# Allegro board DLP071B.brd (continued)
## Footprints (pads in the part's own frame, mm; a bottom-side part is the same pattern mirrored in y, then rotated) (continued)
CAP-FK-V-CASEE_PAN
  rect 1.422x4.166 smd: 1(0,-2.857) 2(0,2.857)
CAP_0402
  rect 0.508x0.508 smd: 1(-0.521,0) 2(0.521,0)
CAP_0603
  rect 1.067x1.016 smd: 1(-0.864,0) 2(0.864,0)
CAP_0805
  rect 1.27x1.524 smd: 1(-0.965,0) 2(0.965,0)
CAP_1206
  rect 1.575x1.626 smd: 1(-1.714,0) 2(1.714,0)
CAP_1210
  rect 1.575x2.591 smd: 1(-1.397,0) 2(1.397,0)
CN3_53398_MOLEX
  rect 2.108x2.997 smd: (-3.8,-1.85) (3.8,-1.85)
  rect 0.61x1.6 smd: 1(-1.25,1.063) 2(0,1.063) 3(1.25,1.063)
CN120_QTH_SAMTEC
  round 0.762 hole 1.016 unplated: (-19.24,2.03) (19.24,2.03)
  rect 0.305x1.448 smd: 1(-17.25,3.08) 2(-17.25,-3.09) 3(-16.75,3.08) 4(-16.75,-3.09) 5(-16.25,3.08) 6(-16.25,-3.09) 7(-15.75,3.08) 8(-15.75,-3.09) 9(-15.25,3.08) 10(-15.25,-3.09) 11(-14.75,3.08) 12(-14.75,-3.09) 13(-14.25,3.08) 14(-14.25,-3.09) 15(-13.75,3.08) 16(-13.75,-3.09) 17(-13.25,3.08) 18(-13.25,-3.09) 19(-12.75,3.08) 20(-12.75,-3.09) 21(-12.25,3.08) 22(-12.25,-3.09) 23(-11.75,3.08) 24(-11.75,-3.09) 25(-11.25,3.08) 26(-11.25,-3.09) 27(-10.75,3.08) 28(-10.75,-3.09) 29(-10.25,3.08) 30(-10.25,-3.09) 31(-9.75,3.08) 32(-9.75,-3.09) 33(-9.25,3.08) 34(-9.25,-3.09) 35(-8.75,3.08) 36(-8.75,-3.09) 37(-8.25,3.08) 38(-8.25,-3.09) 39(-7.75,3.08) 40(-7.75,-3.09) 41(-7.25,3.08) 42(-7.25,-3.09) 43(-6.75,3.08) 44(-6.75,-3.09) 45(-6.25,3.08) 46(-6.25,-3.09) 47(-5.75,3.08) 48(-5.75,-3.09) 49(-5.25,3.08) 50(-5.25,-3.09) 51(-4.75,3.08) 52(-4.75,-3.09) 53(-4.25,3.08) 54(-4.25,-3.09) 55(-3.75,3.08) 56(-3.75,-3.09) 57(-3.25,3.08) 58(-3.25,-3.09) 59(-2.75,3.08) 60(-2.75,-3.09) 61(2.75,3.08) 62(2.75,-3.09) 63(3.25,3.08) 64(3.25,-3.09) 65(3.75,3.08) 66(3.75,-3.09) 67(4.25,3.08) 68(4.25,-3.09) 69(4.75,3.08) 70(4.75,-3.09) 71(5.25,3.08) 72(5.25,-3.09) 73(5.75,3.08) 74(5.75,-3.09) 75(6.25,3.08) 76(6.25,-3.09) 77(6.75,3.08) 78(6.75,-3.09) 79(7.25,3.08) 80(7.25,-3.09) 81(7.75,3.08) 82(7.75,-3.09) 83(8.25,3.08) 84(8.25,-3.09) 85(8.75,3.08) 86(8.75,-3.09) 87(9.25,3.08) 88(9.25,-3.09) 89(9.75,3.08) 90(9.75,-3.09) 91(10.25,3.08) 92(10.25,-3.09) 93(10.75,3.08) 94(10.75,-3.09) 95(11.25,3.08) 96(11.25,-3.09) 97(11.75,3.08) 98(11.75,-3.09) 99(12.25,3.08) 100(12.25,-3.09) 101(12.75,3.08) 102(12.75,-3.09) 103(13.25,3.08) 104(13.25,-3.09) 105(13.75,3.08) 106(13.75,-3.09) 107(14.25,3.08) 108(14.25,-3.09) 109(14.75,3.08) 110(14.75,-3.09) 111(15.25,3.08) 112(15.25,-3.09) 113(15.75,3.08) 114(15.75,-3.09) 115(16.25,3.08) 116(16.25,-3.09) 117(16.75,3.08) 118(16.75,-3.09) 119(17.25,3.08) 120(17.25,-3.09)
  rect 2.54x0.635 smd: G1(-18.445,0) G4(-1.555,0) G5(1.555,0) G8(18.445,0)
  rect 4.699x0.635 smd: G2(-13.175,0) G3(-6.825,0) G6(6.825,0) G7(13.175,0)
CONN4-52808_MOLEX
  rect 0.61x1.448 smd: 1(-1.501,-1.778) 3(0.5,-1.778)
  rect 0.61x1.651 smd: 2(-0.5,1.778) 4(1.501,1.778)
CONN4-53398-A_MOLEX
  rect 2.108x2.997 smd: (-4.425,-2.913) (4.425,-2.913)
  rect 0.61x1.6 smd: 1(-1.875,0) 2(-0.625,0) 3(0.625,0) 4(1.875,0)
CONN4-67068-1000-A_MOLEX
  round 3.175 hole 2.286: (-5.99,10.28) (6.05,10.28)
  round 1.422 hole 0.914: 1(1.28,14.99) 2(-1.22,14.99) 3(-1.22,12.99) 4(1.28,12.99)
CONN5-53398-0590-A_MOLEX
  rect 2.108x2.997 smd: (-5.05,-1.85) (5.05,-1.85)
  rect 0.61x1.6 smd: 1(-2.5,1.063) 2(-1.25,1.063) 3(0,1.063) 4(1.25,1.063) 5(2.5,1.063)
CONN6-53398-0690-A_MOLEX
  rect 2.108x2.997 smd: (-5.675,-1.85) (5.675,-1.85)
  rect 0.61x1.6 smd: 1(-3.125,1.063) 2(-1.875,1.063) 3(-0.625,1.063) 4(0.625,1.063) 5(1.875,1.063) 6(3.125,1.063)
CONN8-43045-0813_MOLEX
  round 1.524 hole 1.016: (-11.989,3.937) (2.997,3.937) 1(0,0) 2(-2.997,0) 3(-5.994,0) 4(-8.992,0) 5(0,2.997) 6(-2.997,2.997) 7(-5.994,2.997) 8(-8.992,2.997)
CONN10-SQT-RA-REV_SAM
  rect 1.778x1.778 hole 1.27: 1(0,0)
  round 1.778 hole 1.27: 2(0,-1.999) 3(0,-3.998) 4(0,-5.997) 5(0,-7.996) 6(0,-9.995) 7(0,-11.994) 8(0,-13.993) 9(0,-15.992) 10(0,-17.991)
CONN10-SQT_SAM
  rect 1.778x1.778 hole 1.27: 1(0,0)
  round 1.778 hole 1.27: 2(0,-1.999) 3(0,-3.998) 4(0,-5.997) 5(0,-7.996) 6(0,-9.995) 7(0,-11.994) 8(0,-13.993) 9(0,-15.992) 10(0,-17.991)
CONN12-53398_MOLEX
  rect 2.108x2.997 smd: (-9.425,-1.85) (9.425,-1.85)
  rect 0.61x1.6 smd: 1(-6.875,1.063) 2(-5.625,1.063) 3(-4.375,1.063) 4(-3.125,1.063) 5(-1.875,1.063) 6(-0.625,1.063) 7(0.625,1.063) 8(1.875,1.063) 9(3.125,1.063) 10(4.375,1.063) 11(5.625,1.063) 12(6.875,1.063)
CONN12-FH12_HRS
  rect 1.854x2.184 smd: (-4.5,-2.895) (4.5,-2.895)
  rect 0.254x1.016 smd: 1(-2.75,0) 2(-2.25,0) 3(-1.75,0) 4(-1.25,0) 5(-0.75,0) 6(-0.25,0) 7(0.25,0) 8(0.75,0) 9(1.25,0) 10(1.75,0) 11(2.25,0) 12(2.75,0)
CONN12-SMT-TSM-112-SV_SAMTEC
  rect 3.175x1.27 smd: 1(-1.587,-13.97) 2(1.587,-11.43) 3(-1.587,-8.89) 4(1.587,-6.35) 5(-1.587,-3.81) 6(1.587,-1.27) 7(-1.587,1.27) 8(1.587,3.81) 9(-1.587,6.35) 10(1.587,8.89) 11(-1.587,11.43) 12(1.587,13.97)
CONN14-53047_MLX
  rect 1.016x1.016 hole 0.508: 1(0,0)
  round 1.016 hole 0.508: 2(-1.25,0) 3(-2.5,0) 4(-3.75,0) 5(-5,0) 6(-6.25,0) 7(-7.5,0) 8(-8.75,0) 9(-10,0) 10(-11.25,0) 11(-12.5,0) 12(-13.75,0) 13(-15,0) 14(-16.25,0)
CONN14-XF2M-A_OMRON
  rect 1.905x1.524 smd: (-5.003,-3.987) (5.003,-3.987)
  rect 0.254x1.295 smd: 1(3.25,0) 2(2.75,0) 3(2.25,0) 4(1.75,0) 5(1.25,0) 6(0.75,0) 7(0.25,0) 8(-0.25,0) 9(-0.75,0) 10(-1.25,0) 11(-1.75,0) 12(-2.25,0) 13(-2.75,0) 14(-3.25,0)
CONN20-TSM-110-0X-X-DV-A_SAMTEC
  rect 1.27x3.68 smd: 1(-11.43,-2.475) 2(-11.43,2.475) 3(-8.89,-2.475) 4(-8.89,2.475) 5(-6.35,-2.475) 6(-6.35,2.475) 7(-3.81,-2.475) 8(-3.81,2.475) 9(-1.27,-2.475) 10(-1.27,2.475) 11(1.27,-2.475) 12(1.27,2.475) 13(3.81,-2.475) 14(3.81,2.475) 15(6.35,-2.475) 16(6.35,2.475) 17(8.89,-2.475) 18(8.89,2.475) 19(11.43,-2.475) 20(11.43,2.475)
CONN22-B22B-PHD_JST
  rect 1.473x1.473 hole 0.965: 1(0,0)
  round 1.473 hole 0.965: 2(2,0) 3(0,2) 4(2,2) 5(0,4) 6(2,4) 7(0,6) 8(2,6) 9(0,8) 10(2,8) 11(0,10) 12(2,10) 13(0,12) 14(2,12) 15(0,14) 16(2,14) 17(0,16) 18(2,16) 19(0,18) 20(2,18) 21(0,20) 22(2,20)
CONN400-ASP-134486-01_SAM_MOD
  round 1.27 hole 1.27 unplated: (-27.19,0) (27.19,-3.05)
  round 0.64 smd: A01(24.765,-5.715) A02(23.495,-5.715) A03(22.225,-5.715) A04(20.955,-5.715) A05(19.685,-5.715) A06(18.415,-5.715) A07(17.145,-5.715) A08(15.875,-5.715) A09(14.605,-5.715) A10(13.335,-5.715) A11(12.065,-5.715) A12(10.795,-5.715) A13(9.525,-5.715) A14(8.255,-5.715) A15(6.985,-5.715) A16(5.715,-5.715) A17(4.445,-5.715) A18(3.175,-5.715) A19(1.905,-5.715) A20(0.635,-5.715) A21(-0.635,-5.715) A22(-1.905,-5.715) A23(-3.175,-5.715) A24(-4.445,-5.715) A25(-5.715,-5.715) A26(-6.985,-5.715) A27(-8.255,-5.715) A28(-9.525,-5.715) A29(-10.795,-5.715) A30(-12.065,-5.715) A31(-13.335,-5.715) A32(-14.605,-5.715) A33(-15.875,-5.715) A34(-17.145,-5.715) A35(-18.415,-5.715) A36(-19.685,-5.715) A37(-20.955,-5.715) A38(-22.225,-5.715) A39(-23.495,-5.715) A40(-24.765,-5.715) B01(24.765,-4.445) B02(23.495,-4.445) B03(22.225,-4.445) B04(20.955,-4.445) B05(19.685,-4.445) B06(18.415,-4.445) B07(17.145,-4.445) B08(15.875,-4.445) B09(14.605,-4.445) B10(13.335,-4.445) B11(12.065,-4.445) B12(10.795,-4.445) B13(9.525,-4.445) B14(8.255,-4.445) B15(6.985,-4.445) B16(5.715,-4.445) B17(4.445,-4.445) B18(3.175,-4.445) B19(1.905,-4.445) B20(0.635,-4.445) B21(-0.635,-4.445) B22(-1.905,-4.445) B23(-3.175,-4.445) B24(-4.445,-4.445) B25(-5.715,-4.445) B26(-6.985,-4.445) B27(-8.255,-4.445) B28(-9.525,-4.445) B29(-10.795,-4.445) B30(-12.065,-4.445) B31(-13.335,-4.445) B32(-14.605,-4.445) B33(-15.875,-4.445) B34(-17.145,-4.445) B35(-18.415,-4.445) B36(-19.685,-4.445) B37(-20.955,-4.445) B38(-22.225,-4.445) B39(-23.495,-4.445) B40(-24.765,-4.445) C01(24.765,-3.175) C02(23.495,-3.175) C03(22.225,-3.175) C04(20.955,-3.175) C05(19.685,-3.175) C06(18.415,-3.175) C07(17.145,-3.175) C08(15.875,-3.175) C09(14.605,-3.175) C10(13.335,-3.175) C11(12.065,-3.175) C12(10.795,-3.175) C13(9.525,-3.175) C14(8.255,-3.175) C15(6.985,-3.175) C16(5.715,-3.175) C17(4.445,-3.175) C18(3.175,-3.175) C19(1.905,-3.175) C20(0.635,-3.175) C21(-0.635,-3.175) C22(-1.905,-3.175) C23(-3.175,-3.175) C24(-4.445,-3.175) C25(-5.715,-3.175) C26(-6.985,-3.175) C27(-8.255,-3.175) C28(-9.525,-3.175) C29(-10.795,-3.175) C30(-12.065,-3.175) C31(-13.335,-3.175) C32(-14.605,-3.175) C33(-15.875,-3.175) C34(-17.145,-3.175) C35(-18.415,-3.175) C36(-19.685,-3.175) C37(-20.955,-3.175) C38(-22.225,-3.175) C39(-23.495,-3.175) C40(-24.765,-3.175) D01(24.765,-1.905) D02(23.495,-1.905) D03(22.225,-1.905) D04(20.955,-1.905) D05(19.685,-1.905) D06(18.415,-1.905) D07(17.145,-1.905) D08(15.875,-1.905) D09(14.605,-1.905) D10(13.335,-1.905) D11(12.065,-1.905) D12(10.795,-1.905) D13(9.525,-1.905) D14(8.255,-1.905) D15(6.985,-1.905) D16(5.715,-1.905) D17(4.445,-1.905) D18(3.175,-1.905) D19(1.905,-1.905) D20(0.635,-1.905) D21(-0.635,-1.905) D22(-1.905,-1.905) D23(-3.175,-1.905) D24(-4.445,-1.905) D25(-5.715,-1.905) D26(-6.985,-1.905) D27(-8.255,-1.905) D28(-9.525,-1.905) D29(-10.795,-1.905) D30(-12.065,-1.905) D31(-13.335,-1.905) D32(-14.605,-1.905) D33(-15.875,-1.905) D34(-17.145,-1.905) D35(-18.415,-1.905) D36(-19.685,-1.905) D37(-20.955,-1.905) D38(-22.225,-1.905) D39(-23.495,-1.905) D40(-24.765,-1.905) E01(24.765,-0.635) E02(23.495,-0.635) E03(22.225,-0.635) E04(20.955,-0.635) E05(19.685,-0.635) E06(18.415,-0.635) E07(17.145,-0.635) E08(15.875,-0.635) E09(14.605,-0.635) E10(13.335,-0.635) E11(12.065,-0.635) E12(10.795,-0.635) E13(9.525,-0.635) E14(8.255,-0.635) E15(6.985,-0.635) E16(5.715,-0.635) E17(4.445,-0.635) E18(3.175,-0.635) E19(1.905,-0.635) E20(0.635,-0.635) E21(-0.635,-0.635) E22(-1.905,-0.635) E23(-3.175,-0.635) E24(-4.445,-0.635) E25(-5.715,-0.635) E26(-6.985,-0.635) E27(-8.255,-0.635) E28(-9.525,-0.635) E29(-10.795,-0.635) E30(-12.065,-0.635) E31(-13.335,-0.635) E32(-14.605,-0.635) E33(-15.875,-0.635) E34(-17.145,-0.635) E35(-18.415,-0.635) E36(-19.685,-0.635) E37(-20.955,-0.635) E38(-22.225,-0.635) E39(-23.495,-0.635) E40(-24.765,-0.635) F01(24.765,0.635) F02(23.495,0.635) F03(22.225,0.635) F04(20.955,0.635) F05(19.685,0.635) F06(18.415,0.635) F07(17.145,0.635) F08(15.875,0.635) F09(14.605,0.635) F10(13.335,0.635) F11(12.065,0.635) F12(10.795,0.635) F13(9.525,0.635) F14(8.255,0.635) F15(6.985,0.635) F16(5.715,0.635) F17(4.445,0.635) F18(3.175,0.635) F19(1.905,0.635) F20(0.635,0.635) F21(-0.635,0.635) F22(-1.905,0.635) F23(-3.175,0.635) F24(-4.445,0.635) F25(-5.715,0.635) F26(-6.985,0.635) F27(-8.255,0.635) F28(-9.525,0.635) F29(-10.795,0.635) F30(-12.065,0.635) F31(-13.335,0.635) F32(-14.605,0.635) F33(-15.875,0.635) F34(-17.145,0.635) F35(-18.415,0.635) F36(-19.685,0.635) F37(-20.955,0.635) F38(-22.225,0.635) F39(-23.495,0.635) F40(-24.765,0.635) G01(24.765,1.905) G02(23.495,1.905) G03(22.225,1.905) G04(20.955,1.905) G05(19.685,1.905) G06(18.415,1.905) G07(17.145,1.905) G08(15.875,1.905) G09(14.605,1.905) G10(13.335,1.905) G11(12.065,1.905) G12(10.795,1.905) G13(9.525,1.905) G14(8.255,1.905) G15(6.985,1.905) G16(5.715,1.905) G17(4.445,1.905) G18(3.175,1.905) G19(1.905,1.905) G20(0.635,1.905) G21(-0.635,1.905) G22(-1.905,1.905) G23(-3.175,1.905) G24(-4.445,1.905) G25(-5.715,1.905) G26(-6.985,1.905) G27(-8.255,1.905) G28(-9.525,1.905) G29(-10.795,1.905) G30(-12.065,1.905) G31(-13.335,1.905) G32(-14.605,1.905) G33(-15.875,1.905) G34(-17.145,1.905) G35(-18.415,1.905) G36(-19.685,1.905) G37(-20.955,1.905) G38(-22.225,1.905) G39(-23.495,1.905) G40(-24.765,1.905) H01(24.765,3.175) H02(23.495,3.175) H03(22.225,3.175) H04(20.955,3.175) H05(19.685,3.175) H06(18.415,3.175) H07(17.145,3.175) H08(15.875,3.175) H09(14.605,3.175) H10(13.335,3.175) H11(12.065,3.175) H12(10.795,3.175) H13(9.525,3.175) H14(8.255,3.175) H15(6.985,3.175) H16(5.715,3.175) H17(4.445,3.175) H18(3.175,3.175) H19(1.905,3.175) H20(0.635,3.175) H21(-0.635,3.175) H22(-1.905,3.175) H23(-3.175,3.175) H24(-4.445,3.175) H25(-5.715,3.175) H26(-6.985,3.175) H27(-8.255,3.175) H28(-9.525,3.175) H29(-10.795,3.175) H30(-12.065,3.175) H31(-13.335,3.175) H32(-14.605,3.175) H33(-15.875,3.175) H34(-17.145,3.175) H35(-18.415,3.175) H36(-19.685,3.175) H37(-20.955,3.175) H38(-22.225,3.175) H39(-23.495,3.175) H40(-24.765,3.175) J01(24.765,4.445) J02(23.495,4.445) J03(22.225,4.445) J04(20.955,4.445) J05(19.685,4.445) J06(18.415,4.445) J07(17.145,4.445) J08(15.875,4.445) J09(14.605,4.445) J10(13.335,4.445) J11(12.065,4.445) J12(10.795,4.445) J13(9.525,4.445) J14(8.255,4.445) J15(6.985,4.445) J16(5.715,4.445) J17(4.445,4.445) J18(3.175,4.445) J19(1.905,4.445) J20(0.635,4.445) J21(-0.635,4.445) J22(-1.905,4.445) J23(-3.175,4.445) J24(-4.445,4.445) J25(-5.715,4.445) J26(-6.985,4.445) J27(-8.255,4.445) J28(-9.525,4.445) J29(-10.795,4.445) J30(-12.065,4.445) J31(-13.335,4.445) J32(-14.605,4.445) J33(-15.875,4.445) J34(-17.145,4.445) J35(-18.415,4.445) J36(-19.685,4.445) J37(-20.955,4.445) J38(-22.225,4.445) J39(-23.495,4.445) J40(-24.765,4.445) K01(24.765,5.715) K02(23.495,5.715) K03(22.225,5.715) K04(20.955,5.715) K05(19.685,5.715) K06(18.415,5.715) K07(17.145,5.715) K08(15.875,5.715) K09(14.605,5.715) K10(13.335,5.715) K11(12.065,5.715) K12(10.795,5.715) K13(9.525,5.715) K14(8.255,5.715) K15(6.985,5.715) K16(5.715,5.715) K17(4.445,5.715) K18(3.175,5.715) K19(1.905,5.715) K20(0.635,5.715) K21(-0.635,5.715) K22(-1.905,5.715) K23(-3.175,5.715) K24(-4.445,5.715) K25(-5.715,5.715) K26(-6.985,5.715) K27(-8.255,5.715) K28(-9.525,5.715) K29(-10.795,5.715) K30(-12.065,5.715) K31(-13.335,5.715) K32(-14.605,5.715) K33(-15.875,5.715) K34(-17.145,5.715) K35(-18.415,5.715) K36(-19.685,5.715) K37(-20.955,5.715) K38(-22.225,5.715) K39(-23.495,5.715) K40(-24.765,5.715)
DIO-SMA
  rect 2.489x1.702 smd: 1(-2.007,0) 2(2.007,0)
DIO-SMB
  rect 2.4x2.4 smd: 1(-2.2,0) 2(2.2,0)
FLTR_0603
  rect 1.067x1.016 smd: 1(-0.864,0) 2(0.864,0)
HDR1X3-TMM1030X-X-S_SAM
  rect 1.524x1.524 hole 1.016: 1(-2,0)
  round 1.524 hole 1.016: 2(0,0) 3(2,0)
HDR2_2MM
  rect 1.651x1.651 hole 1.143: 1(0,0)
  round 1.651 hole 1.143: 2(2,0)
HDR10X2-5103308_TYCO
  round 1.651 hole 1.067: 1(0,0) 2(2.54,0) 3(0,-2.54) 4(2.54,-2.54) 5(0,-5.08) 6(2.54,-5.08) 7(0,-7.62) 8(2.54,-7.62) 9(0,-10.16) 10(2.54,-10.16) 11(0,-12.7) 12(2.54,-12.7) 13(0,-15.24) 14(2.54,-15.24) 15(0,-17.78) 16(2.54,-17.78) 17(0,-20.32) 18(2.54,-20.32) 19(0,-22.86) 20(2.54,-22.86)
IND2-7447789002-7332_WURTH
  rect 1.803x2.21 smd: 1(0,-2.95) 2(0,2.95)
IND_0805
  rect 1.27x1.524 smd: 1(-0.965,0) 2(0.965,0)
IND_SERH
  rect 1.702x3.81 smd: 1(-2.85,0) 2(2.85,0)
IND_SRR1005
  rect 2.997x2.794 smd: 1(5.144,0) 2(-5.144,0)
JACK3-DCPOWER_CUI_MOD
  oval 1.5x3.5 hole 1x3: GND1(6,0)
  oval 3.5x1.5 hole 3x1: GND2(3,4.7)
  oval 1.5x4 hole 1x3.5: P12V_IN(0,0)
KYCON-CN9SMTA
  round 3.81 hole 3.048 unplated: (-12.495,0.775) (12.495,0.775)
  round 0.762 hole 1.524 unplated: (-7.95,0.775) (7.95,0.775)
  rect 0.8x3.7 smd: 1(-5.54,1.325) 2(-2.77,1.325) 3(0,1.325) 4(2.77,1.325) 5(5.54,1.325) 6(-4.155,1.325) 7(-1.385,1.325) 8(1.385,1.325) 9(4.155,1.325)
LCC8-MXD2125_MEMSIC
  round 0.5 smd: (0,0.65)
  rect 1.678x0.894 smd: 1(-1.815,1.27) 2(-1.815,0) 3(-1.815,-1.27) 5(1.815,-1.27) 6(1.815,0) 7(1.815,1.27)
  rect 0.894x1.678 smd: 4(0,-1.815) 8(0,1.815)
LED-0402-REV
  rect 0.508x0.508 smd: 1(0.521,0) 2(-0.521,0)
MH276-157GND-A
  round 7.01 hole 3.988: 1(0,0)
MICTOR_HPA
  round 1.27 hole 2.388 unplated: (11.43,0)
  rect 0.432x1.27 smd: 1(5.715,3.531) 2(5.715,-3.531) 3(5.08,3.531) 4(5.08,-3.531) 5(4.445,3.531) 6(4.445,-3.531) 7(3.81,3.531) 8(3.81,-3.531) 9(3.175,3.531) 10(3.175,-3.531) 11(2.54,3.531) 12(2.54,-3.531) 13(1.905,3.531) 14(1.905,-3.531) 15(1.27,3.531) 16(1.27,-3.531) 17(0.635,3.531) 18(0.635,-3.531) 19(0,3.531) 20(0,-3.531) 21(-0.635,3.531) 22(-0.635,-3.531) 23(-1.27,3.531) 24(-1.27,-3.531) 25(-1.905,3.531) 26(-1.905,-3.531) 27(-2.54,3.531) 28(-2.54,-3.531) 29(-3.175,3.531) 30(-3.175,-3.531) 31(-3.81,3.531) 32(-3.81,-3.531) 33(-4.445,3.531) 34(-4.445,-3.531) 35(-5.08,3.531) 36(-5.08,-3.531) 37(-5.715,3.531) 38(-5.715,-3.531)
  round 1.397 hole 0.889: G1(-5.08,0) G2(-2.54,0) G3(0,0) G4(2.54,0) G5(5.08,0)
POT-3314G
  rect 1.321x1.321 smd: 1(-1.156,2.756) 3(1.156,2.756)
  rect 1.981x1.321 smd: 2(0,-2.756)
PQFP24-QFN-25_SI
  oval 1.016x0.305 smd: 1(-2,1.25) 6(-2,-1.25) 13(2,-1.25) 18(2,1.25)
  rect 1.016x0.305 smd: 2(-2,0.75) 3(-2,0.25) 4(-2,-0.25) 5(-2,-0.75) 14(2,-0.75) 15(2,-0.25) 16(2,0.25) 17(2,0.75)
  oval 0.305x1.016 smd: 7(-1.25,-2) 12(1.25,-2) 19(1.25,2) 24(-1.25,2)
  rect 0.305x1.016 smd: 8(-0.75,-2) 9(-0.25,-2) 10(0.25,-2) 11(0.75,-2) 20(0.75,2) 21(0.25,2) 22(-0.25,2) 23(-0.75,2)
  round 0.61 hole 0.305: 25(-0.889,0.889)
QF48_PPAD
  rect 1.524x0.254 smd: 1(-4.445,2.752) 2(-4.445,2.252) 3(-4.445,1.751) 4(-4.445,1.251) 5(-4.445,0.751) 6(-4.445,0.25) 7(-4.445,-0.25) 8(-4.445,-0.751) 9(-4.445,-1.251) 10(-4.445,-1.751) 11(-4.445,-2.252) 12(-4.445,-2.752) 25(4.445,-2.752) 26(4.445,-2.252) 27(4.445,-1.751) 28(4.445,-1.251) 29(4.445,-0.751) 30(4.445,-0.25) 31(4.445,0.25) 32(4.445,0.751) 33(4.445,1.251) 34(4.445,1.751) 35(4.445,2.252) 36(4.445,2.752)
  rect 0.254x1.524 smd: 13(-2.752,-4.445) 14(-2.252,-4.445) 15(-1.751,-4.445) 16(-1.251,-4.445) 17(-0.751,-4.445) 18(-0.25,-4.445) 19(0.25,-4.445) 20(0.751,-4.445) 21(1.251,-4.445) 22(1.751,-4.445) 23(2.252,-4.445) 24(2.752,-4.445) 37(2.752,4.445) 38(2.252,4.445) 39(1.751,4.445) 40(1.251,4.445) 41(0.751,4.445) 42(0.25,4.445) 43(-0.25,4.445) 44(-0.751,4.445) 45(-1.251,4.445) 46(-1.751,4.445) 47(-2.252,4.445) 48(-2.752,4.445)
RES_0402
  rect 0.508x0.508 smd: 1(-0.521,0) 2(0.521,0)
RES_0603
  rect 1.067x1.016 smd: 1(-0.864,0) 2(0.864,0)
RES_0805
  rect 1.27x1.524 smd: 1(-0.965,0) 2(0.965,0)
RES_1206
  rect 1.575x1.626 smd: 1(-1.714,0) 2(1.714,0)
RES_1210
  rect 1.575x2.591 smd: 1(-1.397,0) 2(1.397,0)
RES_2010
  rect 1.778x2.591 smd: 1(-2.21,0) 2(2.21,0)
RNET8-EXB38V_PAN
  rect 0.94x0.787 smd: 1(-0.8,1.314) 4(-0.8,-1.314) 5(0.8,-1.314) 8(0.8,1.314)
  rect 0.94x0.559 smd: 2(-0.8,0.4) 3(-0.8,-0.4) 6(0.8,-0.4) 7(0.8,0.4)
RNET16-EXB-2HV_PAN
  rect 0.686x0.305 smd: 1(-0.851,1.75) 2(-0.851,1.25) 3(-0.851,0.75) 4(-0.851,0.25) 5(-0.851,-0.25) 6(-0.851,-0.75) 7(-0.851,-1.25) 8(-0.851,-1.75) 9(0.851,-1.75) 10(0.851,-1.25) 11(0.851,-0.75) 12(0.851,-0.25) 13(0.851,0.25) 14(0.851,0.75) 15(0.851,1.25) 16(0.851,1.75)
SM_TO_252_DPAK
  rect 1.6x2.997 smd: 1(-2.286,-4.318) 2(0,-4.318) 3(2.286,-4.318)
  rect 6.198x5.791 smd: 4(0,2.642)
SMC_ST
  rect 2.794x3.81 smd: 1(-3.569,0) 2(3.569,0)
SMD_49
  rect 5.643x2.007 smd: 1(-4.671,0) 2(4.671,0)
SOD-123
  rect 1.016x1.27 smd: 1(-1.778,0) 2(1.778,0)
SOIC5-DBV_TI
  rect 1.321x0.61 smd: 1(-1.187,0.95) 2(-1.187,0) 3(-1.187,-0.95) 4(1.187,-0.95) 5(1.187,0.95)
SOIC6-DBV_TI
  rect 1.321x0.61 smd: 1(-1.187,0.95) 2(-1.187,0) 3(-1.187,-0.95) 4(1.187,-0.95) 5(1.187,0) 6(1.187,0.95)
SOIC6-DRL_TI
  rect 0.356x1.067 smd: 1(-0.5,-0.828) 2(0,-0.828) 3(0.5,-0.828) 4(0.5,0.828) 5(0,0.828) 6(-0.5,0.828)
SOIC8-D_TI
  rect 1.55x0.6 smd: 1(-2.7,1.905) 2(-2.7,0.635) 3(-2.7,-0.635) 4(-2.7,-1.905) 5(2.7,-1.905) 6(2.7,-0.635) 7(2.7,0.635) 8(2.7,1.905)
SOIC8-DDA_TI
  rect 0.635x1.651 smd: 1(-1.905,-2.667) 2(-0.635,-2.667) 3(0.635,-2.667) 4(1.905,-2.667) 5(1.905,2.667) 6(0.635,2.667) 7(-0.635,2.667) 8(-1.905,2.667)
  round 0.61 hole 0.305: 9(-1.27,-0.635)
SOIC8-PW_TI
  rect 0.356x1.524 smd: 1(-0.975,-2.96) 2(-0.325,-2.96) 3(0.325,-2.96) 4(0.975,-2.96) 5(0.975,2.96) 6(0.325,2.96) 7(-0.325,2.96) 8(-0.975,2.96)
SOIC14-PW_TI
  rect 0.305x1.778 smd: 1(-1.951,-2.794) 2(-1.301,-2.794) 3(-0.65,-2.794) 4(0,-2.794) 5(0.65,-2.794) 6(1.301,-2.794) 7(1.951,-2.794) 8(1.951,2.794) 9(1.301,2.794) 10(0.65,2.794) 11(0,2.794) 12(-0.65,2.794) 13(-1.301,2.794) 14(-1.951,2.794)
SOIC16-PW_TI
  rect 0.356x1.524 smd: 1(-2.275,-2.96) 2(-1.625,-2.96) 3(-0.975,-2.96) 4(-0.325,-2.96) 5(0.325,-2.96) 6(0.975,-2.96) 7(1.625,-2.96) 8(2.275,-2.96) 9(2.275,2.96) 10(1.625,2.96) 11(0.975,2.96) 12(0.325,2.96) 13(-0.325,2.96) 14(-0.975,2.96) 15(-1.625,2.96) 16(-2.275,2.96)
SOIC20-DGV_TI
  rect 0.254x1.524 smd: 1(-1.8,-2.921) 2(-1.4,-2.921) 3(-1,-2.921) 4(-0.6,-2.921) 5(-0.2,-2.921) 6(0.2,-2.921) 7(0.6,-2.921) 8(1,-2.921) 9(1.4,-2.921) 10(1.8,-2.921) 11(1.8,2.921) 12(1.4,2.921) 13(1,2.921) 14(0.6,2.921) 15(0.2,2.921) 16(-0.2,2.921) 17(-0.6,2.921) 18(-1,2.921) 19(-1.4,2.921) 20(-1.8,2.921)
SOIC24-PW_TI
  rect 0.356x1.524 smd: 1(-3.575,-2.96) 2(-2.925,-2.96) 3(-2.275,-2.96) 4(-1.625,-2.96) 5(-0.975,-2.96) 6(-0.325,-2.96) 7(0.325,-2.96) 8(0.975,-2.96) 9(1.625,-2.96) 10(2.275,-2.96) 11(2.925,-2.96) 12(3.575,-2.96) 13(3.575,2.96) 14(2.925,2.96) 15(2.275,2.96) 16(1.625,2.96) 17(0.975,2.96) 18(0.325,2.96) 19(-0.325,2.96) 20(-0.975,2.96) 21(-1.625,2.96) 22(-2.275,2.96) 23(-2.925,2.96) 24(-3.575,2.96)
SOIC56-DGG_TI
  rect 0.305x1.524 smd: 1(-6.75,-3.775) 2(-6.25,-3.775) 3(-5.75,-3.775) 4(-5.25,-3.775) 5(-4.75,-3.775) 6(-4.25,-3.775) 7(-3.75,-3.775) 8(-3.25,-3.775) 9(-2.75,-3.775) 10(-2.25,-3.775) 11(-1.75,-3.775) 12(-1.25,-3.775) 13(-0.75,-3.775) 14(-0.25,-3.775) 15(0.25,-3.775) 16(0.75,-3.775) 17(1.25,-3.775) 18(1.75,-3.775) 19(2.25,-3.775) 20(2.75,-3.775) 21(3.25,-3.775) 22(3.75,-3.775) 23(4.25,-3.775) 24(4.75,-3.775) 25(5.25,-3.775) 26(5.75,-3.775) 27(6.25,-3.775) 28(6.75,-3.775) 29(6.75,3.775) 30(6.25,3.775) 31(5.75,3.775) 32(5.25,3.775) 33(4.75,3.775) 34(4.25,3.775) 35(3.75,3.775) 36(3.25,3.775) 37(2.75,3.775) 38(2.25,3.775) 39(1.75,3.775) 40(1.25,3.775) 41(0.75,3.775) 42(0.25,3.775) 43(-0.25,3.775) 44(-0.75,3.775) 45(-1.25,3.775) 46(-1.75,3.775) 47(-2.25,3.775) 48(-2.75,3.775) 49(-3.25,3.775) 50(-3.75,3.775) 51(-4.25,3.775) 52(-4.75,3.775) 53(-5.25,3.775) 54(-5.75,3.775) 55(-6.25,3.775) 56(-6.75,3.775)
SOT23-3_FC
  rect 1.016x1.372 smd: 1(0.94,1.092) 2(-0.94,1.092) 3(0,-1.092)
SOT23-DBV_TI
  rect 0.508x1.372 smd: 1(-0.94,-1.219) 2(0,-1.219) 3(0.94,-1.219) 4(0.94,1.219) 5(-0.94,1.219)
SOT23AVXC
  rect 1.016x1.372 smd: 1(0,-1.092) 2(-0.94,1.092) 3(0.94,1.092)
SOT23AVXD
  rect 1.016x1.372 smd: 1(-0.94,1.092) 2(0.94,1.092) 3(0,-1.092)
SOT223
  rect 1.499x2.007 smd: 1(-2.299,-3.15) 2(0,-3.15) 3(2.299,-3.15)
  rect 3.81x2.007 smd: 4(0,3.15)
SOT_323
  rect 0.762x1.067 smd: 1(0.66,0.94) 2(-0.66,0.94) 3(0,-0.94)
SSOP_8
  rect 0.305x1.6 smd: 1(-0.975,-2.235) 2(-0.325,-2.235) 3(0.325,-2.235) 4(0.975,-2.235) 5(0.975,2.136) 6(0.325,2.136) 7(-0.325,2.136) 8(-0.975,2.136)
SW_GT12
  rect 3.175x0.762 smd: (-2.603,2.54) (-2.603,-2.54) (2.603,0) 1(2.603,2.54) 3(2.603,-2.54)
TP
  round 1.219 hole 0.711: 1(0,0)
TSOP_56_48_DUAL_SKT
  round 1.27 hole 1.27 unplated: (-5.08,4.743) (5.08,4.743)
  rect 1.778x0.305 smd: 1(-9.69,6.75) 2(-9.69,6.25) 3(-9.69,5.75) 4(-9.69,5.25) 5(-9.69,4.75) 6(-9.69,4.25) 7(-9.69,3.75) 8(-9.69,3.25) 9(-9.69,2.75) 10(-9.69,2.25) 11(-9.69,1.75) 12(-9.69,1.25) 13(-9.69,0.75) 14(-9.69,0.25) 15(-9.69,-0.25) 16(-9.69,-0.75) 17(-9.69,-1.25) 18(-9.69,-1.75) 19(-9.69,-2.25) 20(-9.69,-2.75) 21(-9.69,-3.25) 22(-9.69,-3.75) 23(-9.69,-4.25) 24(-9.69,-4.75) 25(-9.69,-5.25) 26(-9.69,-5.75) 27(-9.69,-6.25) 28(-9.69,-6.75) 29(9.69,-6.75) 30(9.69,-6.25) 31(9.69,-5.75) 32(9.69,-5.25) 33(9.69,-4.75) 34(9.69,-4.25) 35(9.69,-3.75) 36(9.69,-3.25) 37(9.69,-2.75) 38(9.69,-2.25) 39(9.69,-1.75) 40(9.69,-1.25) 41(9.69,-0.75) 42(9.69,-0.25) 43(9.69,0.25) 44(9.69,0.75) 45(9.69,1.25) 46(9.69,1.75) 47(9.69,2.25) 48(9.69,2.75) 49(9.69,3.25) 50(9.69,3.75) 51(9.69,4.25) 52(9.69,4.75) 53(9.69,5.25) 54(9.69,5.75) 55(9.69,6.25) 56(9.69,6.75)
TSOPII_44
  rect 0.61x1.143 smd: 1(-8.4,-5.55) 2(-7.6,-5.55) 3(-6.8,-5.55) 4(-6,-5.55) 5(-5.2,-5.55) 6(-4.4,-5.55) 7(-3.6,-5.55) 8(-2.8,-5.55) 9(-2,-5.55) 10(-1.2,-5.55) 11(-0.4,-5.55) 12(0.4,-5.55) 13(1.2,-5.55) 14(2,-5.55) 15(2.8,-5.55) 16(3.6,-5.55) 17(4.4,-5.55) 18(5.2,-5.55) 19(6,-5.55) 20(6.8,-5.55) 21(7.6,-5.55) 22(8.4,-5.55) 23(8.4,5.55) 24(7.6,5.55) 25(6.8,5.55) 26(6,5.55) 27(5.2,5.55) 28(4.4,5.55) 29(3.6,5.55) 30(2.8,5.55) 31(2,5.55) 32(1.2,5.55) 33(0.4,5.55) 34(-0.4,5.55) 35(-1.2,5.55) 36(-2,5.55) 37(-2.8,5.55) 38(-3.6,5.55) 39(-4.4,5.55) 40(-5.2,5.55) 41(-6,5.55) 42(-6.8,5.55) 43(-7.6,5.55) 44(-8.4,5.55)
TSSOP_8
  rect 0.406x1.803 smd: 1(-0.975,-2.954) 2(-0.325,-2.954) 3(0.325,-2.954) 4(0.975,-2.954) 5(0.975,2.954) 6(0.325,2.954) 7(-0.325,2.954) 8(-0.975,2.954)
TSSOP_14
  rect 0.305x1.778 smd: 1(-1.951,-2.794) 2(-1.301,-2.794) 3(-0.65,-2.794) 4(0,-2.794) 5(0.65,-2.794) 6(1.301,-2.794) 7(1.951,-2.794) 8(1.951,2.794) 9(1.301,2.794) 10(0.65,2.794) 11(0,2.794) 12(-0.65,2.794) 13(-1.301,2.794) 14(-1.951,2.794)
unnamed#2
  round 2.362 hole 2.349 unplated: (-20.955,20.955) (-20.955,-20.955) (20.955,20.955) (20.955,-20.955)
  round 0.635 hole 0.66 unplated: (-18.989,-18.989) (18.989,18.989)
unnamed#3
  round 0.762 smd: (0,0)
VISHAY_IR_TSOP348
  rect 1.575x1.575 hole 1.067: 1(0,0)
  round 1.575 hole 1.067: 2(2.54,0) 3(5.08,0)

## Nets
GND: C1.1 C2.2 C3.2 C4.2 C5.2 C7.2 C8.2 C9.2 C10.2 C11.2 C12.2 C13.2 C14.2 C15.1 C16.1 C18.1 C19.2 C20.2 C22.1 C23.1 C24.2 C25.2 C26.1 C27.1 C29.1 C30.1 C31.1 C32.1 C33.1 C34.1 C35.1 C37.1 C38.1 C39.1 C40.1 C41.1 C42.1 C503.1 C504.1 C506.1 C508.1 C509.1 C511.1 C512.1 C513.2 C515.1 C516.1 C517.1 C518.1 C519.1 C520.1 C521.1 C522.1 C523.2 C524.1 C525.1 C526.2 C527.2 C528.2 C529.2 C530.2 C531.2 C532.2 C533.2 C534.2 C535.2 C536.2 C537.2 C538.2 C539.1 C540.2 C541.2 C542.2 C543.2 C544.2 C547.2 C548.1 C552.1 C553.2 C554.2 C555.2 C556.2 C557.2 C558.2 C559.2 C560.2 C561.2 C562.2 C563.2 C564.2 C565.2 C566.2 C567.2 C568.2 C569.2 C570.2 C571.2 C572.2 C573.1 C574.1 C575.2 C576.2 C577.2 C578.2 C579.2 C580.2 C581.2 C582.2 C583.2 C584.2 C585.2 C586.2 C587.2 C588.2 C589.2 C590.2 C591.2 C592.2 C593.2 C594.2 C595.2 C596.2 C597.2 C598.2 C599.2 C600.2 C601.2 C602.2 C603.1 C604.1 C605.1 C606.2 C607.1 C608.2 C611.1 C612.1 C613.2 C614.2 C615.2 C616.2 C617.2 C618.2 C619.2 C620.2 C621.2 C622.2 C623.2 C624.2 C625.2 C626.2 C627.2 C628.2 C629.1 C630.1 C631.2 C632.1 C633.1 C635.2 C636.2 C637.2 C638.2 C639.2 C640.1 C641.1 C643.1 C644.1 C645.1 C646.1 C647.1 C648.1 C649.1 C650.1 C651.1 C652.1 C653.1 C654.2 C655.1 C656.1 C657.1 C658.1 C659.1 C660.1 C661.1 C662.1 C663.1 C664.1 C665.1 C666.1 C667.1 C668.1 C669.1 C670.1 C671.1 C672.1 C673.1 C674.1 C675.1 C676.1 D1.2 D2.2 D3.2 D4.2 D6.2 D7.2 D8.2 D9.2(CATHODE) D10.2(CATHODE) D501.2 D502.2 D503.2 D504.2 D505.2 D506.2 D507.2 DN500.1 DN501.1 DN502.1 DN503.1 DN505.1 DN506.1 DN507.1 DN508.1 J1.G1 J1.G2 J1.G3 J1.G4 J1.G5 J1.G6 J1.G7 J1.G8 J2.G1 J2.G2 J2.G3 J2.G4 J2.G5 J2.G6 J2.G7 J2.G8 J4.4 J5.2 J6.2 J7.5 J8.2 J14.5 J15.5 J16.5 J17.5 J18.7 J18.10 J18.15 J18.16 J19.1 J19.16 J19.17 J19.18 J19.19 J19.20 J20.2 J22.GND1 J22.GND2(3) J23.4 J23.6 J23.8 J23.10 J23.12 J23.14 J23.16 J23.18 J23.20 J24.5 J25.3 J26.3 J27.5 J27.G1 J27.G2 J27.G3 J27.G4 J27.G5 J28.9 J28.10 J28.11 J28.12 J30.3 J32.1 J32.3 J32.5 J32.7 J33.1 J35.13 J35.14 J36.4 J37.3 J38.3 J39.3 J42.6 J43.6 J45.2 J47.9 J47.10 J47.14 J48.2 J49.4 J50.4 J51.4 J52.3 J53.3 J54.3 J54.5 J54.7 J54.9 J54.11 J55.3 J57.3 J59.3 J60.3 J61.3 J62.3 J63.A01 J63.A03 J63.A04 J63.A05 J63.A07 J63.A08 J63.A09 J63.A11 J63.A12 J63.A13 J63.A15 J63.A16 J63.A17 J63.A19 J63.A20 J63.A21 J63.A23 J63.A24 J63.A25 J63.A27 J63.A28 J63.A29 J63.A31 J63.A32 J63.A33 J63.A35 J63.A36 J63.A37 J63.A39 J63.A40 J63.B02 J63.B03 J63.B05 J63.B06 J63.B07 J63.B09 J63.B10 J63.B11 J63.B13 J63.B14 J63.B15 J63.B17 J63.B18 J63.B19 J63.B22 J63.B23 J63.B25 J63.B26 J63.B27 J63.B29 J63.B30 J63.B31 J63.B33 J63.B34 J63.B35 J63.B37 J63.B38 J63.B39 J63.C01 J63.C03 J63.C04 J63.C05 J63.C07 J63.C08 J63.C09 J63.C12 J63.C13 J63.C16 J63.C17 J63.C20 J63.C21 J63.C24 J63.C25 J63.C28 J63.C29 J63.C32 J63.C33 J63.C36 J63.C38 J63.C40 J63.D02 J63.D03 J63.D06 J63.D07 J63.D10 J63.D13 J63.D16 J63.D19 J63.D22 J63.D25 J63.D28 J63.D37 J63.D39 J63.E01 J63.E04 J63.E05 J63.E08 J63.E11 J63.E14 J63.E17 J63.E20 J63.E23 J63.E26 J63.E29 J63.E32 J63.E35 J63.E38 J63.E40 J63.F02 J63.F03 J63.F06 J63.F09 J63.F12 J63.F15 J63.F18 J63.F21 J63.F24 J63.F27 J63.F30 J63.F33 J63.F36 J63.F39 J63.G01 J63.G04 J63.G05 J63.G08 J63.G11 J63.G14 J63.G17 J63.G20 J63.G23 J63.G26 J63.G29 J63.G32 J63.G35 J63.G38 J63.G40 J63.H03 J63.H06 J63.H09 J63.H12 J63.H15 J63.H18 J63.H21 J63.H24 J63.H27 J63.H30 J63.H33 J63.H36 J63.H39 J63.J01 J63.J04 J63.J05 J63.J08 J63.J11 J63.J14 J63.J17 J63.J20 J63.J23 J63.J26 J63.J29 J63.J32 J63.J35 J63.J38 J63.J40 J63.K02 J63.K03 J63.K06 J63.K09 J63.K12 J63.K15 J63.K18 J63.K21 J63.K24 J63.K27 J63.K30 J63.K33 J63.K36 J63.K39(GND#K39) MT1.1 MT2.1 MT3.1 MT4.1 MT5.1 MT6.1 Q3.1(EMITTER) Q4.1(EMITTER) Q501.1(EMITTER) Q502.1(EMITTER) Q503.1(EMITTER) Q504.1(EMITTER) Q507.1(EMITTER) R6.2 R31.2 R44.2 R60.2 R510.1 R516.2 R521.2 R523.1 R526.1 R529.1 R534.1 R559.2 R562.1 R571.1 R572.1 R573.1 R603.1 R604.1 R605.1 R617.1 R632.1 R646.1 R651.2 R652.1 R661.1 R663.1 R665.1 R670.2 R683.2 R688.2 R690.2 R721.2 R724.1 R736.1 R744.2 R745.2 R757.1 R764.1 RN500.5 RN500.6 RN500.7 RN500.8 RN501.5 RN501.6 RN501.7 RN501.8 RN502.5 RN502.6 RN502.7 RN502.8 TP36.1 U1.2 U2.7 U2.19 U2.44 U3.3 U3.7 U4.8 U4.19 U4.38 U4.49 U5.2 U5.3 U6.15 U7.5 U7.9 U8.1 U8.12 U8.13 U9.4 U10.4 U11.A1 U11.A2 U11.A3 U11.A17 U11.A18 U11.A24 U11.A25 U11.A26 U11.AA6 U11.AA9 U11.AA12 U11.AA15 U11.AA18 U11.AA21 U11.AB5 U11.AB14 U11.AB15 U11.AB16 U11.AB17 U11.AB22 U11.AC4 U11.AC6 U11.AC17 U11.AC18 U11.AC23 U11.AD3 U11.AD17 U11.AD18 U11.AD24 U11.AE3 U11.AE17 U11.AE24 U11.AE25 U11.AF1 U11.AF2 U11.AF3 U11.AF17 U11.AF24 U11.AF25 U11.AF26 U11.B1 U11.B2 U11.B3 U11.B17 U11.B18 U11.B25 U11.C3 U11.C18 U11.C24 U11.D4 U11.D17 U11.D18 U11.D23 U11.E5 U11.E15 U11.E16(VTEST4) U11.E17 U11.E22 U11.F6 U11.F9 U11.F12 U11.F15 U11.F18 U11.F21 U11.G5 U11.J5 U11.J6 U11.J21 U11.K5 U11.K26 U11.L5 U11.L12 U11.L13 U11.L14 U11.L15 U11.L23 U11.L25 U11.M6 U11.M11 U11.M12 U11.M13 U11.M14 U11.M15 U11.M16 U11.M21 U11.M22 U11.M25 U11.N5 U11.N11 U11.N12 U11.N13 U11.N14 U11.N15 U11.N16 U11.P11 U11.P12 U11.P13 U11.P14 U11.P15 U11.P16 U11.P24 U11.R5 U11.R6 U11.R11 U11.R12 U11.R13 U11.R14 U11.R15 U11.R16 U11.R24 U11.R26 U11.T12 U11.T13 U11.T14 U11.T15 U11.U5 U11.V5 U11.V6 U11.V21 U11.W5 U11.Y5 U12.15 U13.12 U13.34 U14.1 U14.33 U14.52 U14.56 U15.7 U15.19 U15.44 U16.4 U16.7(WP) U18.3 U19.3 U20.2 U21.19 U21.25 U22.2 U500.3 U501.8 U501.10 U502.2 U503.3 U504.3 U505.14(VSS) U506.3 U507.8 U507.10 U507.11 U508.1 U508.3 U509.2 U509.8 U509.10 U510.1 U510.3 U511.1 U511.2 U512.4 U513.3 U514.2 U514.3 U515.1 U515.12 U515.13 U516.1 U516.7 U516.8 U516.9 U516.10 U516.19 U517.1 U517.9 U517.10 U517.12 U517.13 U518.3 U519.4 U520.1 U520.3 U521.1 U521.3 U522.1 U522.3 U523.3 U524.1 U524.3 VR1.1 VR2.1
P5V: C3.1 C5.1 C672.2 J1.9 J1.11 J2.9 J2.11 J14.8 J15.8 J53.1 J54.1 Q506.2(S) R27.1 R618.1 R698.2 R746.2 R766.1 R777.1 TP25.1
P5V_CONN: J32.4 R698.1
P5V_IR: C506.2 R508.1 U1.3
P5V_IR_CONN: C42.2 R74.1 U22.3
P12V: C19.1 C20.1 C505.2 C512.2 C518.2 C519.2 C606.1 C607.2 C609.2 C631.1 C632.2 C633.2 C639.1 C673.2 DN500.2 DN501.2 DN502.2 DN503.2 DN505.2 DN506.2 DN507.2 DN508.2 J18.2 J31.2 J35.1 J35.2 J52.1 J63.C35 J63.C37 Q5.2 Q5.4 R2.1 R16.2 R22.2 R550.1 R611.2 R691.1 R700.1 R701.1 R718.2 R719.2 R720.2 R747.2 R748.2 R749.2 TP43.1 U2.9 U2.22 U2.23 U2.27 U2.37 U2.42 U2.43 U7.8 U15.9 U15.22 U15.27 U15.37 U15.42
P12V_FIL: C33.2 C36.1 FB1.2 J31.1 Q5.3(S) R45.2 R47.1 R48.1 TP45.1
P12V_IN: C32.2 FB1.1 J22.P12V_IN J32.6
VDD1_INDEX_SENSE: C670.2 J57.1 R771.1
VDD2_INDEX_SENSE: C671.2 J55.1 R772.1
VDD_TILT: C508.2 R515.1 U3.8
3D_TOGGLE: U11.E26 U517.8 U520.2
A1P8V: R558.1 R594.1
A1P8V_SENSE: C27.2 C610.2 R594.2 R610.1 R616.2 TP32.1 U15.29
A_BLU_PWM: J18.5 J19.7 U8.21
A_GRN_PWM: J18.3 J19.5 U8.22
A_LED4_PWM: J18.9 J19.2 U8.20
A_LED5_PWM: J18.11 J19.4 U8.19
A_LED6_PWM: J18.13 J19.6 U8.18
A_LED7_PWM: J18.17 J19.11 U8.17
A_LED8_PWM: J18.19 J19.13 U8.16
A_RED_PWM: J18.1 J19.3 U8.23
A_SPARE_1: J18.18 J33.2 U517.23
A_SPARE_2: J18.22 U8.15(Y9)
A_SPARE_3: J18.20 U8.14
A_SSP0_CLK: R37.2 R38.2 R680.2 TP46.1 U11.AD4
A_SSP0_RXD: R625.1 R671.1 R672.1 U11.AD5
A_SSP0_TXD: R621.1 R623.1 U11.AB7
ADC_CSZ: J54.10 R597.1 TP64.1
ADC_RST/COMP_PWM: J54.2 R596.1 R694.2 TP55.1
ADC_SCLK: J54.4 R598.1 TP56.1
ADC_SDIN: J21.1 J54.6 TP57.1
ADC_SDO: J29.1 J54.8 TP58.1
AFE_CLK: R579.2 U11.AD12
AFE_RSTZ: J2.108 R9.1 U11.AC12
ALF_CLAMP: J2.116 U11.AB12
ALF_COAST: J2.118 U11.AC11
ALF_CSYNC: J2.49 TP2.1 U11.AE11
ALF_HSYNC: J2.51 TP24.1 U11.AD11
ALF_VSYNC: J2.50 TP1.1 U11.AF11
BLU_LED_EN: J40.1 RN500.3 U517.7
BLU_PWM: RN501.2 U8.4 U11.C20
BT656_A_CLK: J2.94 U4.5
BT656_A_D0: J2.105 U4.28
BT656_A_D1: J2.104 U4.26
BT656_A_D2: J2.103 U4.24
BT656_A_D3: J2.102 U4.22
BT656_A_D4: J2.101 U4.20
BT656_A_D5: J2.100 U4.16
BT656_A_D6: J2.99 U4.14
BT656_A_D7: J2.98 U4.12
BT656_A_D8: J2.97 U4.10
BT656_A_D9: J2.96 U4.7
BT656_B_CLK: J1.94 U4.4
BT656_B_D0: J1.105 U4.27
BT656_B_D1: J1.104 U4.25
BT656_B_D2: J1.70 J1.103 R503.1 U4.23
BT656_B_D3: J1.102 U4.21
BT656_B_D4: J1.101 U4.18
BT656_B_D5: J1.100 U4.15
BT656_B_D6: J1.99 R557.1 U4.13
BT656_B_D7: J1.98 U4.11
BT656_B_D8: J1.97 U4.9
BT656_B_D9: J1.96 U4.6
BT656_CLK: R537.2 U4.52
BT656_D0: R547.2 U4.30
BT656_D1: R546.2 U4.32
BT656_D2: R545.2 U4.34
BT656_D3: R544.2 U4.36
BT656_D4: R543.2 U4.39
BT656_D5: R542.2 U4.41
BT656_D6: R541.2 U4.43
BT656_D7: R540.2 U4.45
BT656_D8: R539.2 U4.47
BT656_D9: R538.2 U4.50
BUS_SELECT: J2.89 R745.1 U21.16
COMP_SENSE_INPUT: J26.2 R704.1 U512.2
COMP_SENSE_VDD: C649.2 J26.1 R703.1
COMP_SENSOR: J21.3 R705.1 R706.1 U512.1
CSZ5_DAD2: J63.B28 R65.1
CW_INDEX1: J1.82 R750.1 R751.1 TP61.1 U11.AF7 U519.1
CW_INDEX2: R568.2 R753.1 R755.1 TP60.1 U519.7(OUT)
CW_PWM1: R32.1 U11.AD8
CW_PWM2/SPD4: R517.1 U11.H26 U515.7
CWCTR1: C549.1 C550.1 C551.1 DN508.3 J58.1 U15.13
CWCTR2: C500.1 C501.1 C502.1 DN502.3 J56.1 U2.13
CWY1A: DN505.3 J58.4 R576.2 R609.2
CWY1B: DN506.3 J58.3 R25.2 R577.2
CWY1C: DN507.3 J58.2 R28.2 R563.2
CWY2A: DN500.3 J56.4 R7.2 R500.2
CWY2B: DN501.3 J56.3 R5.2 R501.2
CWY2C: DN503.3 J56.2 R4.2 R502.2
DA0: C615.1 R628.1 U11.AB8
DA1: C616.1 R629.1 U11.AF4
DA2: C618.1 R673.1 U11.AE5
DA3: C621.1 R635.1 U11.AD6
DADADD0: J63.A14 R628.2
DADADD1: J63.A18 R629.2
DADADD2: J63.A22 R673.2
DADADD3: J63.A26 R635.2
DADINTZ: J63.B08 R595.2 R713.2
DADMD0: J63.A06 R634.2
DADMD1: J63.A10 R627.2
DADOEZ: J63.B04 R633.2 R714.2
DADSEL0: J63.A30 R626.2
DADSEL1: J63.A34 R630.2
DADSTB: J63.A38 R636.2 TP47.1
DB/RED_PWM: R757.2 RN500.4 U8.2 U11.B19 U521.2
DINTZ: C578.1 R595.1 U11.AC8
DM0: C620.1 R634.1 U11.AE6
DM1: C614.1 R627.1 U11.AD7
DMD_P3P3V: C35.2 C39.2 FB2.1 FB3.1 J46.2 R66.1 R712.1 R713.1 R714.1
DMDP3P3VA: C40.2 FB3.2 J63.C39
DMDP3P3VB: C34.2 FB2.2 J63.D38
DMDSPARE0: J63.B16 R44.1
DOEZ: C619.1 R633.1 U11.AE7
DRV_RST/SSP2_CSZ_1: U11.K22 U516.6
DS0: C613.1 R626.1 U11.AC7
DS1: C617.1 R630.1 U11.AE4
DSP_P1P8V: C10.1 C13.1 J1.6 J1.8 J2.6 J2.8 J12.2
DSTB: C622.1 R636.1 U11.AF5
DYN_BLK_BUF: R756.2 U521.4
EXT_ARSTZ: J63.A02 R8.2 R10.1 R767.1 TP4.1 U11.T24
EXT_CLK: J2.52 R579.1
FAN1_LOCKD: J59.2 R71.1 U11.B24
FAN1_SW: D507.1(C) L505.2 R770.1 U15.40
FAN2_LOCKD: J60.2 R72.1 U11.D21
FAN2_SW: D506.1(C) L504.2 R769.1 U15.39
FAN3_LOCKD: J61.2 R73.1 U11.C23
FAN3_SW: D505.1(C) L503.2 R768.1 U15.38
FAN4_LOCKD: J37.2 R57.1 R581.2
FAN4_SW: D504.1(C) L502.2 R734.1 U2.40
FAN5_LOCKD: J38.2 R58.1 R567.2
FAN5_SW: D503.1(C) J3.1 L501.2 R733.1 U2.39
FAN6_LOCKD: J39.2 R59.1 R583.2
FAN6_SW: D502.1(C) J3.3 L500.2 R732.1
FAN6_SW_JUMP: J3.2 U2.38
FE_P1P2V: C9.1 C12.1 J1.2 J1.4 J2.2 J2.4 J13.2
FE_RST: J36.1 R56.2 U18.2
FIELD: J2.88 J36.3 U11.AF9
FLASH_A19_A21: R687.2 R689.2 U14.11
FLASH_A21_VPP: R685.1 R686.2 U14.15
FLASH_CSSZ: R585.2 U14.32
FLASH_CSZ: R585.1 U11.E12
FLASH_RSTZ: R552.1 R553.1 U14.14
FREQ_SENSOR: J25.2 J29.3
GPIO_12: R513.1 R514.1 U11.B22
GPIO_13: R13.1 R14.1 U11.C21
GPIO_21: RN503.3 U8.10 U11.E20
GPIO_23: RN503.4 U8.11 U11.E21
GPIO_24: J9.2 U11.B26
GPIO_26: J40.2 U11.D24
GPIO_30: R564.2 U11.D25
GPIO_32: R565.2 U11.E24
GPIO_33: R560.2 U11.D26
GPIO_40: R547.1 U11.T23
GPIO_41: R546.1 U11.R22
GPIO_42: R545.1 U11.U26
GPIO_43: R544.1 U11.U25
GPIO_44: R543.1 U11.U24
GPIO_45: R542.1 U11.U23
GPIO_46: R541.1 U11.T22
GPIO_47: R540.1 U11.V26
GPIO_48: R539.1 U11.V25
GPIO_49: R538.1 U11.V24
GPIO_50: R537.1 U11.V23
GPIO_54: RN502.4 U11.F26 U517.2
GPIO_60: R580.1 R581.1 U11.H22
GPIO_61: R566.1 R567.1 U11.H23
GPIO_62: R569.1 R570.1 U11.H24
GPIO_63: R561.1 R568.1 U11.H25
GPIO_65: R582.1 R583.1 U11.J22
GPIO_74: J21.2 U11.AE10
GPIO_75: J29.2 R599.1
GPIO_81: J24.4 U11.AB10
GPIOX_11: R67.1 U21.12
GPIOX_12: R68.1 U21.13
GPIOX_13: R69.1 U21.14
GPIOX_14: R70.1 U21.15
GPIOX_INT: R737.1 U11.E3 U21.24
GPIOX_RST: R744.1 U11.G22 U21.20
GRN_LED_EN: RN500.2 U11.C25 U517.6
GRN_PWM: RN501.1 U8.3 U11.B20
HDMI_CEC: J2.13 TP5.1 U11.G23
HDMI_HPD: J2.90 U21.10
HDMI_INT: J2.91 TP18.1 U11.AB13
HOLD_BOOTZ: J8.1 R548.2 U11.F24
I2C_BUSY: J36.2 R735.2 U11.G24
ICE_RSTZ: J23.15 J27.9 R697.1 U510.2 U511.4(\ \R\E\S\E\T)
ICTSEN: R559.1 U11.M24
INDEX1_SENSE_INPUT: J57.2 R752.1 U519.2
INDEX2_SENSE_INPUT: J55.2 R754.1 U519.6
IR0: U11.C26 U500.4
IR1: U11.E23 U518.4
KEYPD_DOWN: J47.4 R731.1 U21.2
KEYPD_LED_HOT: R725.2 U21.9
KEYPD_LED_LMP: R741.2 U21.8
KEYPD_LED_PWR: R742.2 U21.7
KEYPD_LEFT: J47.5 R729.1 U21.3
KEYPD_PWR: J47.7 R588.1 R727.1 U19.2
KEYPD_PWR_BUF: U19.4 U21.1
KEYPD_RIGHT: J47.6 R730.1 U21.4
KEYPD_SEL: J47.2 R743.1 U21.6
KEYPD_UP: J47.3 R728.1 U21.5
LAMPLITZ: J33.4 J34.1 J48.1 R774.1 R775.1
LAMPLITZ_FLTR: C675.2 R775.2 TP63.1 U522.2
LED1_GRN: D14.2(CATHODE) R68.2
LED1_RED: D15.2(CATHODE) R67.2
LED2_GRN: D12.2(CATHODE) R70.2
LED2_RED: D13.2(CATHODE) R69.2
LED4_PWM: RN501.3 U8.5 U11.A20
LED5_PWM: RN501.4 U8.6 U11.A21
LED6_PWM: RN502.1 U8.7 U11.B21
LED7_PWM: RN502.2 U8.8 U11.A22
LED8_PWM: RN502.3 U8.9 U11.A23
LED_DIN: J43.2 J44.3 R721.1 R722.2 TP50.1
LED_DIR: J43.5 R739.2 TP51.1
LED_DOUT: J43.3 R759.2 TP53.1
LED_EN: J33.3 J41.2
LED_OE: J43.4 R761.2 TP52.1
LED_SCLK: J43.1 R758.2 TP54.1
LMP_HOT: J6.1 J9.3 R528.2
LMP_TXD: J40.3 R763.1 R764.2 U524.2
LMP_TXD_BUF: J48.5 R778.1
LMPCTRL: R668.2 R670.1 TP22.1 U11.AC9 U508.2 U517.3
LMPCTRL_BUF: J48.6 R622.1
LMPCTRL_Z: J48.4 R669.1
LMPSTAT: U11.AF8 U522.4
LP_DRIVE: R574.1 R575.1 U505.5
LP_IR0: R590.1 U1.1 U500.2
LP_IR1: R593.1 U22.1 U518.2
LP_P1_0: R588.2 U505.2
LP_P1_5: R590.2 U505.7
LP_P1_6: R593.2 U505.8
LP_P2_6: R591.2 U505.13
LP_P2_7: R592.2 U505.12
LP_P3P3V: C503.2 C504.2 R504.1 R505.1 U500.5(VCC) U518.5(VCC)
LP_TA0: R589.2 U505.3
LP_TCK: J17.2 R608.1
LP_TDO_TDI: C605.2 J17.4 R606.1 U505.10
LP_TEST_VPP: J17.3 R608.2 U505.11
M_DCLKA_N: J63.K05 U11.V3
M_DCLKA_P: J63.K04 U11.V4
M_DCLKB_N: J63.J03 U11.J4
M_DCLKB_P: J63.J02 U11.J3
M_DDA00_N: J63.D21 U11.P3
M_DDA00_P: J63.D20 U11.P4
M_DDA01_N: J63.C23 U11.P1
M_DDA01_P: J63.C22 U11.P2
M_DDA02_N: J63.H23 U11.R3
M_DDA02_P: J63.H22 U11.R4
M_DDA03_N: J63.G22 U11.R1
M_DDA03_P: J63.G21 U11.R2
M_DDA04_N: J63.H26 U11.T3
M_DDA04_P: J63.H25 U11.T4
M_DDA05_N: J63.G25 U11.T1
M_DDA05_P: J63.G24 U11.T2
M_DDA06_N: J63.D24 U11.U3
M_DDA06_P: J63.D23 U11.U4
M_DDA07_N: J63.H29 U11.U1
M_DDA07_P: J63.H28 U11.U2
M_DDA08_N: J63.G28 U11.W3
M_DDA08_P: J63.G27 U11.W4
M_DDA09_N: J63.D27 U11.W1
M_DDA09_P: J63.D26 U11.W2
M_DDA10_N: J63.C27 U11.Y1
M_DDA10_P: J63.C26 U11.Y2
M_DDA11_N: J63.H32 U11.Y3
M_DDA11_P: J63.H31 U11.Y4
M_DDA12_N: J63.G31 U11.AA1
M_DDA12_P: J63.G30 U11.AA2
M_DDA13_N: J63.H35 U11.AA3
M_DDA13_P: J63.H34 U11.AA4
M_DDA14_N: J63.G34 U11.AB1
M_DDA14_P: J63.G33 U11.AB2
M_DDA15_N: J63.H38 U11.AC1
M_DDA15_P: J63.H37 U11.AC2
M_DDB00_N: J63.K26 U11.N2
M_DDB00_P: J63.K25 U11.N1
M_DDB01_N: J63.J25 U11.N4
M_DDB01_P: J63.J24 U11.N3
M_DDB02_N: J63.F23 U11.M1
M_DDB02_P: J63.F22 U11.M2
M_DDB03_N: J63.E22 U11.M4
M_DDB03_P: J63.E21 U11.M3
M_DDB04_N: J63.F26 U11.L2
M_DDB04_P: J63.F25 U11.L1
M_DDB05_N: J63.E25 U11.L4
M_DDB05_P: J63.E24 U11.L3
M_DDB06_N: J63.K29 U11.K2
M_DDB06_P: J63.K28 U11.K1
M_DDB07_N: J63.J28 U11.K4
M_DDB07_P: J63.J27 U11.K3
M_DDB08_N: J63.F29 U11.H2
M_DDB08_P: J63.F28 U11.H1
M_DDB09_N: J63.E28 U11.H4
M_DDB09_P: J63.E27 U11.H3
M_DDB10_N: J63.K32 U11.G2
M_DDB10_P: J63.K31 U11.G1
M_DDB11_N: J63.J31 U11.G4
M_DDB11_P: J63.J30 U11.G3
M_DDB12_N: J63.F32 U11.F2
M_DDB12_P: J63.F31 U11.F1
M_DDB13_N: J63.E31 U11.F4
M_DDB13_P: J63.E30 U11.F3
M_DDB14_N: J63.K35 U11.E2
M_DDB14_P: J63.K34 U11.E1
M_DDB15_N: J63.J34 U11.D2
M_DDB15_P: J63.J33 U11.D1
M_SCTRLA_N: J63.G37 U11.V1
M_SCTRLA_P: J63.G36 U11.V2
M_SCTRLB_N: J63.F35 U11.J2
M_SCTRLB_P: J63.F34 U11.J1
MAN_RSTZ: J20.1 R696.1 SW1.3 U511.3
MC_VCC: C547.1 C574.2 R587.2 R606.2 U505.1
MODEB: J45.1 J63.B12 R66.2
MTR_ARSTZ: R36.2 TP15.1 U2.48(RESETZ) U11.T25 U15.48(RESETZ)
OCLKA: R578.1 U2.6 U15.6
OCLKA_RES: R578.2 U11.AF6
OUT1A: R609.1 U15.12
OUT1A_SNUB: C549.2 R576.1
OUT1B: R25.1 U15.15
OUT1B_SNUB: C550.2 R577.1
OUT1C: R28.1 U15.16
OUT1C_SNUB: C551.2 R563.1
OUT2A: R7.1 U2.12
OUT2A_SNUB: C500.2 R500.1
OUT2B: R5.1 U2.15
OUT2B_SNUB: C501.2 R501.1
OUT2C: R4.1 U2.16
OUT2C_SNUB: C502.2 R502.1
P1_A0: J2.85 U11.AE12
P1_A1: J2.84 U11.AF12
P1_A2: J2.83 U11.AF13
P1_A3: J2.82 U11.AF14
P1_A4: J2.81 U11.AC13
P1_A5: J2.80 U11.AD13
P1_A6: J2.79 U11.AE13
P1_A7: J2.78 U11.AE14
P1_A8: J2.77 U11.AE15
P1_A9: J2.76 U11.AD15
P1_B0: J2.75 U11.AD14
P1_B1: J2.74 U11.AC14
P1_B2: J2.73 U11.AF15
P1_B3: J2.72 U11.AF16
P1_B4: J2.71 U11.AE16
P1_B5: J2.70 U11.AD16
P1_B6: J2.69 U11.AC16
P1_B7: J2.68 U11.AC15
P1_B8: J2.67 U11.AB18
P1_B9: J2.66 U11.AF18
P1_C0: J2.65 U11.AE18
P1_C1: J2.64 U11.AC19
P1_C2: J2.63 U11.AF20
P1_C3: J2.62 U11.AF19
P1_C4: J2.61 U11.AE19
P1_C5: J2.60 U11.AD19
P1_C6: J2.59 U11.AF21
P1_C7: J2.58 U11.AE21
P1_C8: J2.57 U11.AE20
P1_C9: J2.56 U11.AD20
P1_HSYNC: J2.86 TP10.1 U11.AD21
P1_VSYNC: J2.55 TP12.1 U11.AC20
P1P1V: C31.2 C544.1 C553.1 C554.1 C557.1 C558.1 C559.1 C561.1 C563.1 C565.1 C566.1 C569.1 C571.1 C575.1 C576.1 C579.1 C581.1 C583.1 C586.1 C588.1 C590.1 C593.1 C594.1 C596.1 C599.1 C601.1 C602.1 C634.2 C635.1 J13.1 R35.2 R536.1 R660.2 R664.2 TP35.1 U11.AA8 U11.AA11 U11.AA14 U11.AA17 U11.AA20 U11.F7 U11.F10 U11.F13 U11.F16 U11.F19 U11.G21 U11.H6 U11.K21 U11.L6 U11.L11 U11.L16 U11.N21 U11.P6 U11.T11 U11.T16 U11.T21 U11.U6 U11.W21 U11.Y6
P1P2V_PMD2: C15.2 C510.2 J13.3 R509.2 R525.2 R527.2 TP14.1
P1P8V: C542.1 C560.1 C567.1 C572.1 C584.1 C585.1 C587.1 C589.1 C591.1 C592.1 C595.1 C600.1 C623.1 C624.1 C625.1 C626.1 C627.1 C628.1 C636.1 C637.1 C638.1 J12.1 R702.1 TP40.1 U11.AA5 U11.AA13 U11.AE1 U11.C1 U11.F5 U11.F14 U11.G6 U11.H5 U11.H21 U11.K6 U11.M5 U11.N6 U11.P5 U11.P21 U11.T5 U11.T6 U11.U21 U11.W6
P1P8V_PMD2: J12.3 R551.1 TP17.1
P2_A0: J2.45 U11.AB19
P2_A1: J2.44 U11.AE23
P2_A2: J2.43 U11.AD22
P2_A3: J2.42 U11.AC21
P2_A4: J2.41 U11.AB20
P2_A5: J2.40 U11.AD23
P2_A6: J2.39 U11.AC22
P2_A7: J2.38 U11.AB21
P2_A8: J2.37 U11.AD25
P2_A9: J2.36 U11.AD26
P2_B0: J2.35 U11.AC24
P2_B1: J2.34 U11.AC25
P2_B2: J2.33 U11.AB23
P2_B3: J2.32 U11.AC26
P2_B4: J2.31 U11.AB24
P2_B5: J2.30 U11.AA22
P2_B6: J2.29 U11.AB25
P2_B7: J2.28 U11.AA23
P2_B8: J2.27 U11.AB26
P2_B9: J2.26 U11.Y22
P2_C0: J2.25 U11.AA24
P2_C1: J2.24 U11.AA25
P2_C2: J2.23 U11.AA26
P2_C3: J2.22 U11.W22
P2_C4: J2.21 U11.Y23
P2_C5: J2.20 U11.Y24
P2_C6: J2.19 U11.Y25
P2_C7: J2.18 U11.Y26
P2_C8: J2.17 U11.V22
P2_C9: J2.16 U11.W23
P2_HSYNC: J2.46 TP7.1 U11.W26
P2_VSYNC: J2.15 TP19.1 U11.U22
P2P5V: C11.1 C14.1 J1.10 J1.12 J2.10 J2.12 Q505.2 Q505.4 R41.1 R43.2 TP39.1
P2P5V_CONN: J32.8 R20.2 R41.2
P2P5V_PMD2: Q500.2 Q500.4 R20.1 R24.2 TP16.1
P3P3V: C2.1 C4.1 C30.2 C38.2 C509.2 C515.2 C520.2 C521.2 C526.1 C538.1 C540.1 C555.1 C556.1 C562.1 C564.1 C568.1 C570.1 C573.2 C577.1 C580.1 C582.1 C597.1 C598.1 C603.2 C604.2 C629.2 C630.2 C646.2 C648.2 C650.2 C651.2 C652.2 C653.2 C654.1 C655.2 C659.2 C660.2 C661.2 C662.2 C663.2 C664.2 C665.2 C674.2 D12.1 D13.1 D14.1 D15.1 DN504.3 J1.5 J1.7 J2.5 J2.7 J23.1 J23.2 J24.1 J25.1 J27.12 J27.14 J46.1 J49.3 J50.3 J51.3 R1.1 R8.1 R11.1 R12.1 R23.2 R34.2 R36.1 R42.2 R56.1 R57.2 R58.2 R59.2 R61.1 R71.2 R72.2 R73.2 R504.2 R507.2 R512.1 R515.2 R520.1 R522.1 R528.1 R530.2 R533.2 R548.1 R549.1 R584.1 R586.1 R600.2 R601.1 R620.1 R637.1 R638.1 R639.1 R640.1 R641.1 R647.1 R649.2 R654.1 R656.1 R658.1 R672.2 R675.2 R676.2 R681.1 R684.1 R685.2 R693.2 R696.2 R697.2 R703.2 R704.2 R706.2 R708.2 R709.2 R710.2 R715.2 R716.2 R717.2 R723.2 R726.2 R728.2 R729.2 R730.2 R731.2 R735.1 R737.2 R740.2 R743.2 R750.2 R752.2 R754.2 R755.2 R760.1 R762.1 R763.2 R765.1 R771.2 R772.2 R774.2 R776.1 RN503.5 RN503.6 RN503.7 RN503.8 TP42.1 U3.4 U4.17(VCC) U8.24 U11.AA7 U11.AA10 U11.AA16 U11.AA19 U11.AE26 U11.F8 U11.F11 U11.F17 U11.F20 U11.L21 U11.R21 U11.Y21 U12.16(VCC) U13.11 U13.33 U14.43 U16.3 U16.8 U18.5(VCC) U20.3 U20.4(V+) U20.5 U21.21(VCC) U503.5(VCC) U504.6(VCC) U506.6(VCC) U510.5(VCC) U511.5 U512.8 U513.5(VCC) U514.5(VCC) U515.24 U516.20 U517.24 U519.8 U520.5(VCC) U521.5(VCC) U522.5(VCC) U523.5 VR1.3 VR2.3
P3P3V_CONN: J32.2 R61.2 R615.2 R667.2
P3P3V_EX: J46.3 R26.2 TP23.1
P3P3V_LP: C37.2 C41.2 C539.2 C548.2 C611.2 C640.2 R46.1 R505.2 R506.2 R511.2 R532.2 R535.2 R575.2 R587.1 R607.1 R614.2 R666.2 R727.2 TP20.1 U17.2 U17.3 U17.6 U17.7(OUT4) U19.5(VCC)
P_CLK1: J2.54 TP6.1 U11.AE22
P_CLK2: J2.14 TP8.1 U11.W25
P_CLK3: J2.119 TP11.1 U11.AF23
P_DATAEN1: J2.87 TP13.1 U11.AF22
P_DATAEN2: J2.47 TP9.1 U11.W24
P_INTZ: R657.1 U2.36
PACKET_RDY: J14.9 J15.9 R603.2 TP30.1 U11.F25 U506.2
PB_INDEX: J14.10 J15.10 J24.2 R605.2 TP21.1 U11.AE9 U506.1
PB_IR_ENABLE: J24.3 U11.AD9
PGOOD: R655.1 U2.35
PIPESTAT0: J27.38 RN504.14
PIPESTAT0R: RN504.3 U11.C6
PIPESTAT1: J27.36 RN504.15
PIPESTAT1R: RN504.2 U11.B5
PIPESTAT2: J27.34 RN504.16
PIPESTAT2R: RN504.1 U11.A4
PLLD_VAD: C535.1 FB506.2 U11.K25
PLLD_VDD: C543.1 FB503.2 U11.L22
PLLM1_VAD: C534.1 FB505.2 U11.L24
PLLM1_VDD: C533.1 FB504.2 U11.L26
PLLM2_VAD: C530.1 FB501.2 U11.R25
PLLM2_VDD: C541.1 FB502.2 U11.P23
PLLS_VAD: C529.1 FB500.2 U11.R23
PLUG_DETECT: J14.7 J15.7 R646.2 TP31.1 U11.F23 U506.5
PM_ADR_0: U11.C7 U13.5 U14.31
PM_ADR_1: U11.A7 U13.4 U14.26
PM_ADR_2: U11.B7 U13.3 U14.25
PM_ADR_3: U11.C8 U13.2 U14.24
PM_ADR_4: U11.D8 U13.1 U14.23
PM_ADR_5: U11.A8 U13.44 U14.22
PM_ADR_6: U11.B8 U13.43 U14.21
PM_ADR_7: U11.C9 U13.42 U14.20
PM_ADR_8: U11.D9 U13.28 U14.10
PM_ADR_9: U11.E9 U13.27 U14.9
PM_ADR_10: U11.A9 U13.26 U14.8
PM_ADR_11: U11.B9 U13.25 U14.7
PM_ADR_12: U11.C10 U13.24 U14.6
PM_ADR_13: U11.D10 U13.23 U14.5
PM_ADR_14: U11.E10 U13.22 U14.4
PM_ADR_15: U11.C11 U13.21 U14.3
PM_ADR_16: U11.D11 U13.20 U14.54
PM_ADR_17: U11.A11 U13.19 U14.19
PM_ADR_18: U11.B11 U13.18 U14.18
PM_ADR_19: R682.1 R689.1 U11.C12
PM_ADR_20: U11.D12 U14.12
PM_ADR_21: R686.1 R687.1 R688.1 U11.E11
PM_ADR_22: R690.1 U11.A12 U14.2
PM_BLS0: R643.1 U11.A6
PM_BLS0S: R643.2 U13.39
PM_BLS1: R644.1 U11.B6
PM_BLS1S: R644.2 U13.40
PM_DAT_0: U11.B13 U13.7 U14.35
PM_DAT_1: U11.C14 U13.8 U14.37
PM_DAT_2: U11.D14 U13.9 U14.39
PM_DAT_3: U11.E13 U13.10 U14.41
PM_DAT_4: U11.A14 U13.13 U14.44
PM_DAT_5: U11.B14 U13.14 U14.46
PM_DAT_6: U11.C15 U13.15 U14.48
PM_DAT_7: U11.D15 U13.16 U14.50
PM_DAT_8: U11.E14 U13.29 U14.36
PM_DAT_9: U11.C16 U13.30 U14.38
PM_DAT_10: U11.D16 U13.31 U14.40
PM_DAT_11: U11.B15 U13.32 U14.42
PM_DAT_12: U11.A15 U13.35 U14.45
PM_DAT_13: U11.A16 U13.36 U14.47
PM_DAT_14: U11.B16 U13.37 U14.49
PM_DAT_15: U11.C17 U13.38 U14.51
PM_OESZ: R645.2 U13.41 U14.34
PM_OEZ: R645.1 U11.C13
PM_SRAM_CSSZ: R642.2 U13.6
PM_SRAM_CSZ: R642.1 U11.D13
PM_WESZ: R602.2 U13.17(WE#) U14.13
PM_WEZ: R602.1 U11.B12
PMD1K2_CP1: C6.1 U2.18
PMD1K2_CP2: C6.2 U2.17
PMD1K2_FB_P2P5V: C524.2 L3.2 R24.1 U2.46
PMD1K2_GD_CORE: Q1.1 U2.26
PMD1K2_VCP: C505.1 U2.21
PMD1K2_VREG: C513.1 U2.20 U2.24 U2.31 U2.45 U2.47
PMD1K_CP1: C28.1 U15.18
PMD1K_CP2: C28.2 U15.17
PMD1K_FB_LIN1: C610.1 R610.2 R651.1 U15.31 U507.4
PMD1K_FB_MOT1: R33.2 U15.11
PMD1K_FB_MOT2: C1.2 L2.1 U2.11
PMD1K_FB_P2P5V: C647.2 L9.2 R43.1 U15.46
PMD1K_FB_P3P3V: C641.2 L8.2 R42.1 U15.45
PMD1K_FB_P5V: C552.2 L5.1 R27.2 U15.24
PMD1K_GD_CORE: Q2.1 U15.26
PMD1K_GM_IN1: C29.2 R32.2 TP33.1 U15.8
PMD1K_GM_IN2: C511.2 R517.2 TP3.1 U2.8
PMD1K_SENSE_MOT1: R31.1 U15.14
PMD1K_SENSE_MOT2: R6.1 U2.14
PMD1K_VCP: C609.1 U15.21
PMD1K_VREG: C608.1 U15.20 U15.47
PMD_INTZ: R657.2 R658.2 R692.1 U11.AE8 U15.36
POSENSE: R553.2 R554.1 R653.2 R654.2 U15.34
POSENSE_FIL: C525.2 R554.2 U11.P22
PSENS: R653.1 U2.34
PWR_OFF_RDY: U11.B23 U505.9
PWR_ON_AC: J30.1 R592.1
PWR_ON_RDY: U11.C22 U505.6
PWRGOOD: R552.2 R655.2 R656.2 U9.1 U9.7 U10.1 U10.7 U11.T26 U15.35 U18.4 U19.1 U500.1 U510.4 U518.1
REAL_CWTACH1: R647.2 U15.5
REAL_CWTACH2: R522.2 U2.5
RED_LED_EN: J9.1 RN500.1 U517.5
RTCK: J23.11 J27.13 R707.1 R709.1
RTCKR: R707.2 U11.E4
SCL: J1.115 J2.115 J10.2
SCL0: J10.3 J49.1 R601.2 R612.2 U5.6 U11.A10 U16.6 U20.1 U21.23
SCL1: J2.95 J10.1 J50.1 R760.2 U11.D20
SCL2: J51.1 R3.1 R512.2 R513.2
SCL2_C: J2.113 R3.2
SCL_VMON: R612.1 U501.9 U507.9 U509.9
SDA: J1.117 J2.117 J11.2
SDA0: J11.3 J49.2 R549.2 R613.2 U5.7 U11.B10 U16.5 U20.6 U21.22
SDA1: J2.93 J11.1 J50.2 R762.2 U11.E19
SDA2: J51.2 R12.2 R13.2 R15.1
SDA2_C: J2.114 R15.2
SDA_VMON: R613.1 U501.7 U507.7 U509.7
SENSE_PULSE: RN503.1 U11.G25 U517.11
SENSE_PULSE_BUF: J18.12 J19.8 J33.12 U517.14
SEQ_SYNC: R631.2 R632.2 U11.AB9
SEQ_SYNC_DUAL: R503.2 R600.1 R631.1
SP_CLK: J35.3 R53.2
SP_D0: J35.4 R49.2
SP_D1: J35.5 R54.2
SP_D2: J35.6 R50.2
SP_D3: J35.7 R55.2
SP_D4: J35.8 R51.2
SP_D5: J35.9 R52.2
SP_D6: J35.10 R63.2
SP_D7: J35.11 R62.2
SP_FB: J35.12 R64.2
SP_STAT_IN: R570.2 U515.14
SP_WAVE_CLK: U11.G26 U515.2
SP_WAVE_D0: R580.2 U515.3
SP_WAVE_D1: R566.2 U515.4
SP_WAVE_D2: R569.2 U515.5
SP_WAVE_D3: R561.2 U515.6
SP_WAVE_D5: R582.2 U515.8
SSI_3D_TOGGLE: J18.14 J19.15 J33.9 U517.17
SSI_STB_B: J18.8 J19.14 J33.8 U517.18
SSI_STB_G: J18.6 J19.12 J33.7 U517.19
SSI_STB_R: J18.4 J19.10 J33.6 U517.20
SSI_SUBFRAME: J18.21 J19.9 J33.5 U517.21
SSP0_CLK: R38.1 U2.2 U15.2
SSP0_CLK_DMD: J63.B32 R37.1
SSP0_CLK_DUAL: J1.62 R680.1
SSP0_CSZ0: R676.1 R677.2 TP44.1 U11.AC5
SSP0_CSZ0_DAD1: J63.B24 R677.1
SSP0_CSZ1: R674.2 R675.1 TP37.1 U11.AB6
SSP0_CSZ1_DMD: J63.C06 R674.1
SSP0_CSZ2: R649.1 R679.2 TP41.1 U11.AC3
SSP0_CSZ2_PMD1: R679.1 U15.4
SSP0_CSZ3: R678.2 R693.1 TP34.1 U11.AB4
SSP0_CSZ3_PMD2: R678.1 U2.4
SSP0_CSZ5/SPD6: R65.2 U11.J23 U515.9
SSP0_RXD: J63.B36 R623.2 R624.2 R648.2 R650.2 R671.2 R712.2 TP49.1
SSP0_RXD_DUAL: J1.74 R624.1
SSP0_TXD: R40.1 U2.3 U15.3
SSP0_TXD_DMD: J63.C02 R39.1
SSP0_TXD_DUAL: J1.66 R619.1
SSP1_CLK: J14.6 J15.6 R564.1 R572.2 TP26.1 U504.5
SSP1_CSZ0: J14.1 J15.1 R560.1 R562.2 TP29.1 U504.1
SSP1_DI: J14.2 J15.2 R604.2 TP28.1 U11.F22 U504.4
SSP1_DO: J14.4 J15.4 R565.1 R571.2 TP27.1 U504.2
SSP2/LED_DIN: R722.1 U513.1
SSP2_CLK: U11.K23 U516.2 U516.3
SSP2_CSZ2/SPD7: U11.J24 U515.10
SSP2_CSZ_0: U11.J26 U516.5
SSP2_DIN: J44.2 U11.K24
SSP2_DO: U11.J25 U516.4
SUBFRAME: RN503.2 U11.D22 U517.4
SW_EN: Q501.3 R550.2 U7.1
SW_SS: C18.2 U7.4
SWNODE2_CORE: D1.1(C) L1.1 Q1.3(S) U2.25
